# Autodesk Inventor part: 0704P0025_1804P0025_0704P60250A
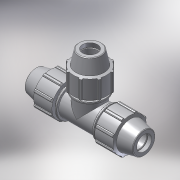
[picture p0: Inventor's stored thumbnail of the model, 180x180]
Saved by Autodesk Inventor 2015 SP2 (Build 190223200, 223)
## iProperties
Created: 2017-02
Part Number: 0704P0025_1804P0025_0704P60250A
Material: PVC-Piping
Description: PLASSON REPAIR TEE 25
Document SubType Name: Modeling
Designer: KIM
Mass: 92.6774 g
Surface Area: 199.44 cm^2
Volume: 66.1981 cm^3
Density: 1.4 g/cm^3
Appearance: Smooth - White
Author: Кирилл
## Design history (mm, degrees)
derived "0704P0.ipt"
feature "Solid1::0704P0.ipt"
tag "TaggingFeature1"
body "Solid1"
other parameters: "d2" = 25, "d4" = 6.5, "d5" = 19.5, "d7" = 54, "d11" = 2.6, "d13" = 120 deg, "d14" = 37.5, "d15" = 12 deg, "d16" = 46.98, "d18" = 1.25, "d19" = 35 deg, "d20" = 17.5 deg, "d21" = 50.22, "d23" = 0, "d25" = 360 deg, "d27" = 1.08, "d33" = 0.5, "d42" = 27.3, "d43" = 1.62, "d46" = 0.75, "d63" = 58, "d67" = 40.5, "d76" = 25, "d77" = 54, "d78" = 12 deg, "d79" = 78, "d80" = 120 deg, "d81" = 37.5, "d82" = 6.5, "d85" = 40.5, "d86" = 46.98, "d87" = 2.6, "d88" = 2.6, "d89" = 19.5, "d90" = 27.3, "d96" = 5.2, "d98" = 50.22, "d99" = 35 deg, "d100" = 17.5 deg, "d102" = 0, "d103" = 1.08, "d107" = 360 deg, "d109" = 0.75, "d112" = 1.25, "d118" = 360 deg, "d121" = 0, "d128" = 156, "d131" = 22.5, "d132" = 22.5, "d133" = 58, "d134" = 1.16, "d135" = 5.2, "d152" = 0, "d154" = 0, "d156" = 0, "d158" = 0, "d_" = 25, "E_" = 54, "A_" = 78, "l_" = 58, "H_" = 156
